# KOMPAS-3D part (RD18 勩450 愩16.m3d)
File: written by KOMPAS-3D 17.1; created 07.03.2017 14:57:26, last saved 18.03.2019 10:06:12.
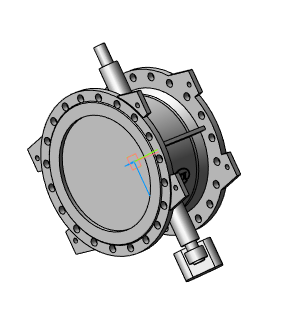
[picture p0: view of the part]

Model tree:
1. Операция без истории:2  (labels: Сталь 20  ГОСТ 1050-88)

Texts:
  RD18 Ду100 Ру16
  RD18 Ду150 Ру16
  RD18 Ду200 Ру16
  RD18 Ду250 Ру16
  RD18 Ду300 Ру16
  RD18 Ду350 Ру16
  RD18 Ду400 Ру10
  RD18 Ду400 Ру16
  RD18 Ду450 Ру10
  RD18 Ду450 Ру16
  RD18 Ду500 Ру10
  RD18 Ду500 Ру16
  RD18 Ду600 Ру10
  RD18 Ду600 Ру16
  RD18 Ду700 Ру10
  RD18 Ду700 Ру16
  RD18 Ду800 Ру10
  RD18 Ду800 Ру16
  RD18 Ду900 Ру10
  RD18 Ду900 Ру16
  RD18 Ду1000 Ру10
  RD18 Ду1000 Ру16
  RD18 Ду1200 Ру16
  RD18 Ду1400 Ру16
